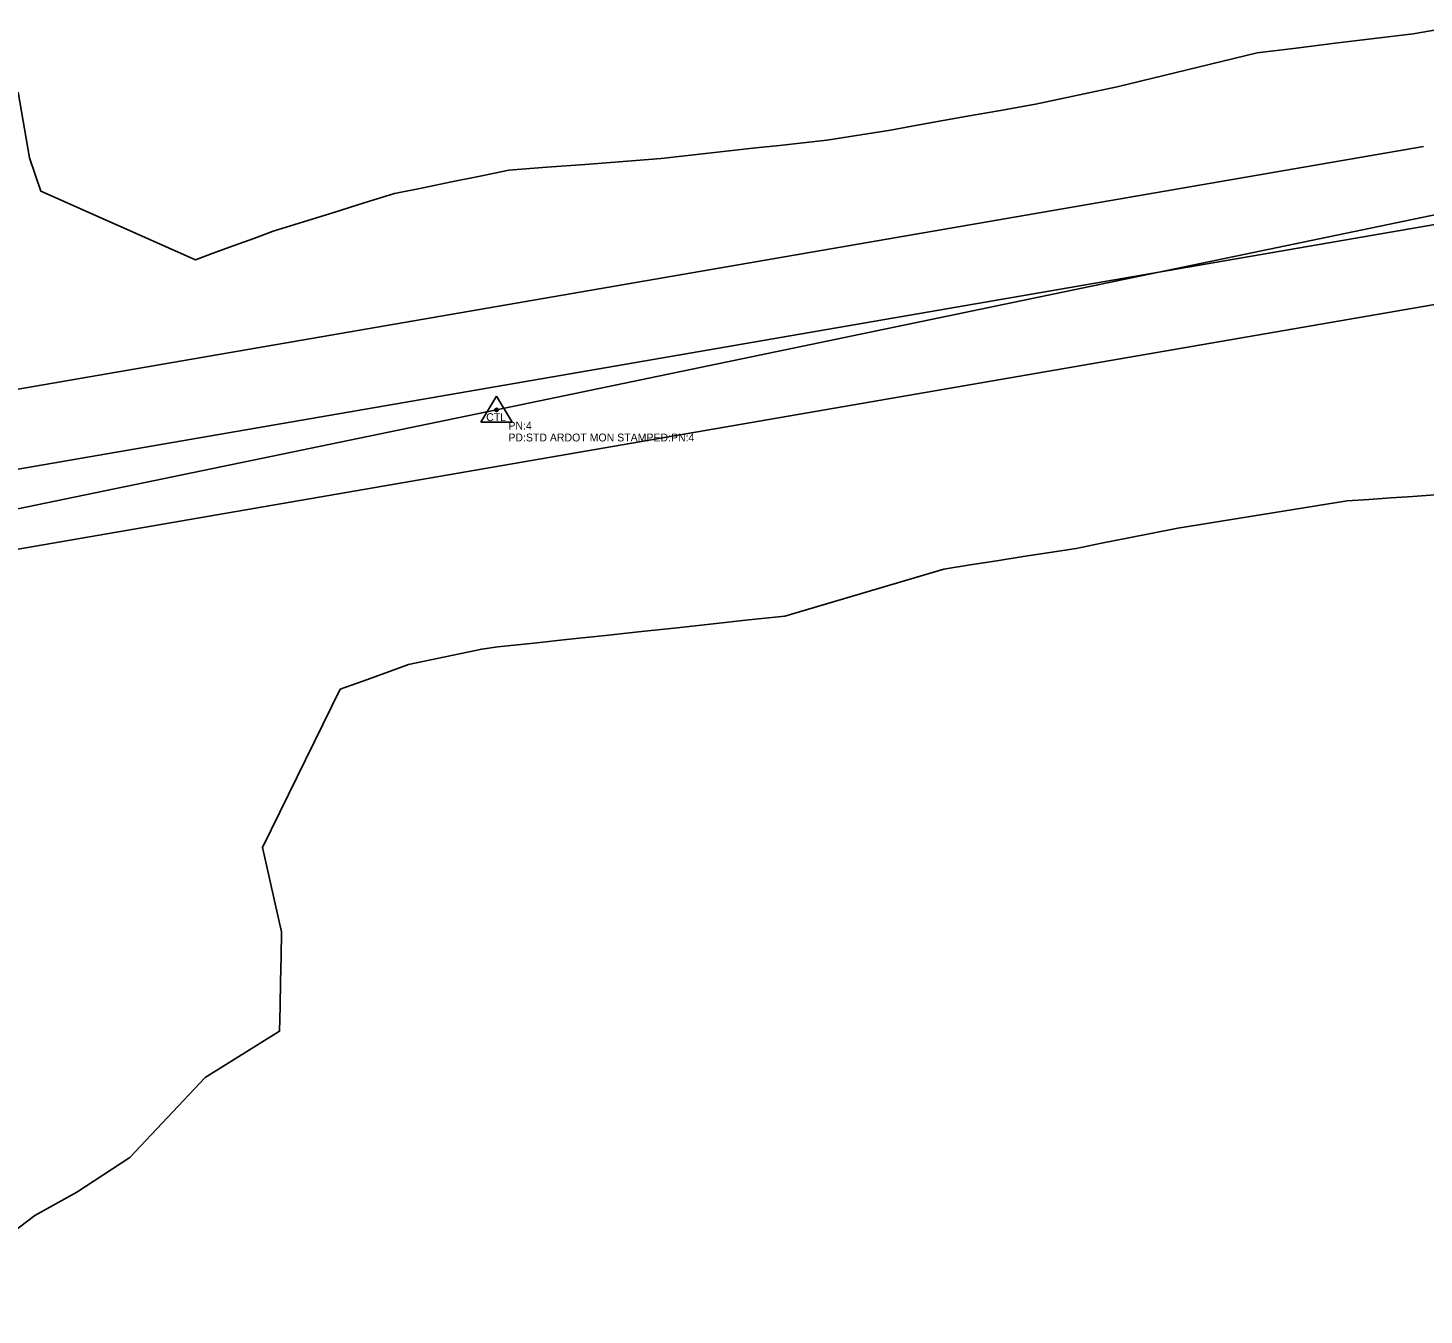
# Model space of a CAD drawing. Extents: x 1734463 to 1738841, y 377458 to 380217.
# Drawn here: x 1736720 to 1737607, y 377869 to 378686 of the extents above; entities that cross this region are included whole.
import ezdxf

# ---------------------------------------------------------------- set-up
doc = ezdxf.new("R2010")
doc.units = 0
for name, color, linetype in [('5', 7, 'Continuous'), ('ROW APPROXIMATE', 7, 'Continuous'), ('S_PRIMARY_CTL_ANNOT', 7, 'Continuous')]:
    doc.layers.add(name, color=color, linetype=linetype)

msp = doc.modelspace()

# ---------------------------------------------------------------- linework, layer by layer
for p, q in [((1737017.96, 378443.92), (1737869.49, 378621.02)), ((1737017.96, 378443.92), (1737869.49, 378621.02)), ((1737017.96, 378443.92), (1737869.49, 378621.02)), ((1737017.96, 378443.92), (1737869.49, 378621.02)), ((1737017.96, 378443.92), (1737869.49, 378621.02)), ((1737017.96, 378443.92), (1737869.49, 378621.02)), ((1735860.82, 378259.15), (1737615.21, 378561.84)), ((1735860.82, 378259.15), (1737615.21, 378561.84)), ((1735860.82, 378259.15), (1737615.21, 378561.84)), ((1736142.34, 378263.18), (1737017.96, 378443.92)), ((1736142.34, 378263.18), (1737017.96, 378443.92)), ((1736142.34, 378263.18), (1737017.96, 378443.92)), ((1736142.34, 378263.18), (1737017.96, 378443.92)), ((1736142.34, 378263.18), (1737017.96, 378443.92)), ((1736142.34, 378263.18), (1737017.96, 378443.92))]:
    msp.add_line(p, q)
for points in [[(1737622.02, 378686.47), (1737600.01, 378682.82), (1737575.27, 378679.79), (1737550.53, 378676.75), (1737525.79, 378673.71), (1737501.05, 378670.67), (1737486.22, 378667.08), (1737471.4, 378663.48), (1737456.57, 378659.89), (1737441.75, 378656.3), (1737426.92, 378652.71), (1737412.09, 378649.11), (1737360.19, 378638.02), (1737337.94, 378634.11), (1737315.68, 378630.2), (1737293.43, 378626.29), (1737280.73, 378623.94), (1737268.04, 378621.6), (1737227.63, 378615.24), (1737212.61, 378613.58), (1737197.59, 378611.92), (1737182.57, 378610.26), (1737167.55, 378608.61), (1737152.53, 378606.95), (1737137.51, 378605.29), (1737122.49, 378603.63), (1737098.31, 378601.74), (1737074.13, 378599.86), (1737049.95, 378597.97), (1737025.77, 378596.08), (1737007.59, 378592.4), (1736989.42, 378588.72), (1736971.24, 378585.04), (1736953.07, 378581.36), (1736933.83, 378575.36), (1736914.59, 378569.37), (1736895.35, 378563.37), (1736876.11, 378557.37), (1736863.74, 378552.84), (1736851.37, 378548.32), (1736839, 378543.8), (1736826.63, 378539.27), (1736728.44, 378582.89), (1736721.35, 378604.08), (1736714.07, 378645.78)], [(1736641.3, 377869.21), (1736724.74, 377932.48), (1736751.34, 377947.32), (1736784.99, 377969.16), (1736832.83, 378020.08), (1736880.17, 378049.37), (1736880.47, 378065.16), (1736880.77, 378080.95), (1736881.07, 378096.74), (1736881.38, 378112.53), (1736877.33, 378130.37), (1736873.27, 378148.21), (1736869.22, 378166.05), (1736918.62, 378266.55), (1736933.09, 378271.77), (1736947.56, 378276.98), (1736962.03, 378282.19), (1737008.57, 378292.09), (1737018.82, 378293.43), (1737041.6, 378295.87), (1737064.37, 378298.32), (1737087.15, 378300.77), (1737109.93, 378303.21), (1737132.7, 378305.66), (1737155.48, 378308.11), (1737178.26, 378310.56), (1737201.03, 378313), (1737301.94, 378342.88), (1737318.79, 378345.51), (1737335.63, 378348.14), (1737352.47, 378350.78), (1737369.32, 378353.41), (1737386.16, 378356.04), (1737402.25, 378359.23), (1737418.35, 378362.43), (1737434.44, 378365.62), (1737450.53, 378368.81), (1737558.08, 378386.23), (1737572.02, 378387.15), (1737585.97, 378388.07), (1737599.91, 378388.99), (1737613.85, 378389.91)]]:
    msp.add_lwpolyline(points)
at = {"layer": '5'}
for p, q in [((1737017.96, 378443.92), (1737869.49, 378621.02)), ((1736142.34, 378263.18), (1737017.96, 378443.92))]:
    msp.add_line(p, q, dxfattribs=at)
at = {"layer": 'ROW APPROXIMATE'}
for p, q in [((1737606.64, 378611.1), (1736295.07, 378384.81)), ((1737623.64, 378512.55), (1736234.19, 378272.83))]:
    msp.add_line(p, q, dxfattribs=at)
at = {"layer": 'S_PRIMARY_CTL_ANNOT'}
for p, q in [((1737017.96, 378452.62), (1737007.93, 378436.11)), ((1737017.96, 378452.62), (1737027.78, 378436.11)), ((1737007.93, 378436.11), (1737027.78, 378436.11))]:
    msp.add_line(p, q, dxfattribs=at)
for radius in [1.04, 0.609, 0.344]:
    msp.add_circle((1737017.96, 378443.92), radius, dxfattribs=at)

# ---------------------------------------------------------------- texts
for s, p in [('CTL', (1737011.37, 378436.85)), ('PN:4', (1737025.46, 378431.42)), ('PD:STD ARDOT MON STAMPED:PN:4', (1737025.46, 378423.92))]:
    msp.add_text(s, height=5, dxfattribs=at).set_placement(p)

doc.saveas('drawing.dxf')
